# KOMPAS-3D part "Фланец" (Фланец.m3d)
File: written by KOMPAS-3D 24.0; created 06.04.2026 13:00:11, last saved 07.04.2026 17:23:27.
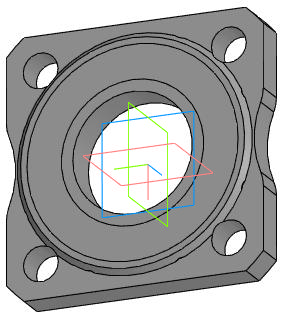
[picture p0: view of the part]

Document properties: Автор: R2D2; Полное имя файла: E:\Работа\Зайцев\Солянка\VSR1-13V-PED-F Клапан запорно-регулирующий DN.ru\DN65\исходные материалы\Фланец.m3d

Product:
- Component [standard]: (unnamed)  | qty 1  | Материал: ВЧ40 ГОСТ 7293-85 (density 7200 kg/m3); Масса: 3.42; additional columns: 65-16-01-2-B-ВЧ40-II-dв 77,5; Фланец; ГОСТ 33259-2015
- Part/product: Фланец
    Масса: 1.756734

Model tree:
1. Эскиз:9
2. Элемент выдавливания:9
     Расстояние 1 = -17
3. Эскиз:6
4. Эскиз:8
5. Элемент выдавливания:8
     Расстояние 2 = 20
6. Элемент выдавливания:10
7. Эскиз:7  (with: Ребро.Элемент выдавливания:10)
8. Элемент выдавливания:11
9. Зеркальный массив:3
10. Экземпляр ( 1 )
11. Экземпляр ( 2 )  (with: Элемент выдавливания:11)
12. Скругление:3  (with: Ребро.Элемент выдавливания:11)  (labels: Ребро.Элемент выдавливания:11.Экземпляр ( 2 ))
     Радиус = 20

Expressions: v520+50
Referenced files in C:\Program Files\ASCON\KOMPAS-3D v24\Libs\PolynomLib\DATA\vault\Methods\Kompas\3D\: PLib_Flange_GOST_33259_1401.m3d
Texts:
  BOSimple***Material:38d6725a-5efe-48e1-b177-a7817acb862a
  BOSimple***PART:f2891aeb-0e31-1664-fa85-580fc2e8217c***SHORTLOC:B6A6_23E38AE8DB154823[II;2;Круглый;65;16;77,5;0;ВЧ40 ГОСТ 7293-85]
  Угловой размер с обрывом
  Ch34
  Плоскость XY.Начало координат
  Ось Z.Начало координат
  Plane ZX. Origin
  Плоскость ZX.Начало координат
